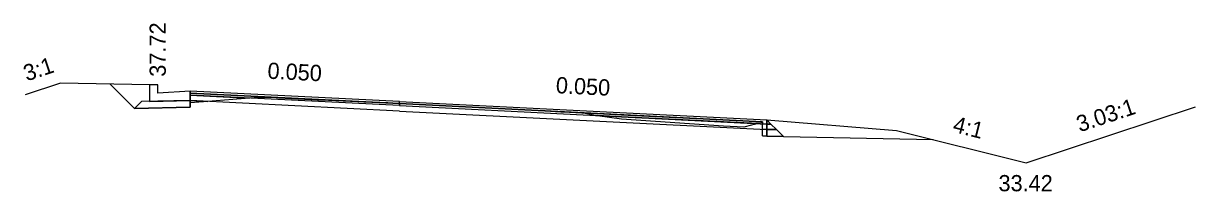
# Model space of a CAD drawing. Extents: x 2192944 to 2203363, y 83241 to 89279.
# Drawn here: x 2203233 to 2203305.3, y 86249.9 to 86260.2 of the extents above; entities that cross this region are included whole.
import ezdxf

# ---------------------------------------------------------------- set-up
doc = ezdxf.new("R2010")
doc.units = 0
for name, color, linetype in [('Prop CMT Conc Surface', 7, 'Continuous'), ('Prop CMT Concrete Structures', 7, 'Continuous'), ('Prop CMT Pvmt Course 1', 7, 'Continuous'), ('Prop CMT Pvmt Course 1 CG', 7, 'Continuous'), ('Prop CMT Pvmt Course 1 Wedge', 7, 'Continuous'), ('Prop CMT Pvmt Course 2', 7, 'Continuous'), ('Prop CMT Pvmt Course 2 Wedge', 7, 'Continuous'), ('Prop CMT Pvmt Course 3', 7, 'Continuous'), ('Prop CMT Pvmt Course 3 Wedge', 7, 'Continuous'), ('Prop CMT Pvmt Surface', 7, 'Continuous'), ('Prop CMT Pvmt Surface Shoulder', 7, 'Continuous'), ('Prop CMT Pvmt Wedge Surface 1', 7, 'Continuous'), ('Prop CMT Pvmt Wedge Surface 2', 7, 'Continuous'), ('Prop CMT Pvmt Wedge Surface 3', 7, 'Continuous'), ('Prop CMT Shld Paved Course 1', 7, 'Continuous'), ('Prop CMT Shld Paved Course 2', 7, 'Continuous'), ('Prop CMT Shld Paved Course 3', 7, 'Continuous'), ('Prop CMT Slope Grass', 7, 'Continuous'), ('Prop CMT Subgrade Earthwork', 7, 'Continuous'), ('Prop XS Ditch Standard Text', 7, 'Continuous'), ('Prop XS Hydro Elevations', 7, 'Continuous'), ('Prop XS SE Text', 7, 'Continuous'), ('Prop XS Side Slope Text', 7, 'Continuous')]:
    doc.layers.add(name, color=color, linetype=linetype)

msp = doc.modelspace()

# ---------------------------------------------------------------- linework, layer by layer
at = {"layer": 'Prop CMT Conc Surface'}
for points in [[(2203241.321, 86255.938), (2203241.32, 86256.438), (2203240.82, 86256.438)], [(2203243.321, 86256.058), (2203241.321, 86255.938)]]:
    msp.add_lwpolyline(points, dxfattribs=at)
at = {"layer": 'Prop CMT Concrete Structures'}
for points in [[(2203243.321, 86256.058), (2203241.321, 86255.938), (2203241.32, 86256.438), (2203240.82, 86256.438)], [(2203240.82, 86256.438), (2203240.821, 86255.424), (2203243.321, 86255.474)], [(2203243.321, 86255.474), (2203243.321, 86256.058)]]:
    msp.add_lwpolyline(points, dxfattribs=at)
at = {"layer": 'Prop CMT Pvmt Course 1'}
for points in [[(2203256.225, 86255.412), (2203243.321, 86256.058)], [(2203243.321, 86256.058), (2203243.321, 86255.808), (2203243.321, 86255.808), (2203243.321, 86255.933)], [(2203243.321, 86255.933), (2203256.225, 86255.287)], [(2203256.225, 86255.162), (2203256.225, 86255.412)], [(2203256.225, 86255.412), (2203278.888, 86254.279)], [(2203256.225, 86255.162), (2203256.225, 86255.412)], [(2203256.225, 86255.287), (2203256.225, 86255.162), (2203256.225, 86255.162)], [(2203278.619, 86254.168), (2203256.225, 86255.287)], [(2203256.225, 86255.287), (2203256.225, 86255.162), (2203256.225, 86255.162)], [(2203278.619, 86254.043), (2203278.619, 86254.168)], [(2203278.888, 86254.029), (2203278.619, 86254.043)], [(2203278.888, 86254.279), (2203278.888, 86254.029)]]:
    msp.add_lwpolyline(points, dxfattribs=at)
at = {"layer": 'Prop CMT Pvmt Course 1 CG'}
for points in [[(2203243.321, 86255.474), (2203240.321, 86255.414), (2203239.896, 86254.989)], [(2203243.321, 86255.058), (2203243.321, 86255.474)], [(2203239.896, 86254.989), (2203243.321, 86255.058)]]:
    msp.add_lwpolyline(points, dxfattribs=at)
at = {"layer": 'Prop CMT Pvmt Course 1 Wedge'}
for points in [[(2203243.321, 86255.933), (2203247.558, 86255.721), (2203248.177, 86255.69), (2203248.63, 86255.667), (2203248.668, 86255.665), (2203248.781, 86255.66), (2203251.17, 86255.54), (2203251.408, 86255.528), (2203253.673, 86255.415), (2203254.034, 86255.397), (2203255.521, 86255.323)], [(2203243.321, 86255.808), (2203243.321, 86255.933)], [(2203255.521, 86255.323), (2203254.034, 86255.391), (2203253.673, 86255.407), (2203251.408, 86255.494), (2203251.17, 86255.503), (2203248.781, 86255.627), (2203248.668, 86255.633), (2203248.63, 86255.634), (2203248.177, 86255.653), (2203247.558, 86255.671), (2203246.981, 86255.625), (2203243.321, 86255.808)], [(2203278.619, 86254.103), (2203278.397, 86254.054), (2203277.937, 86254.077), (2203277.477, 86254.1), (2203276.221, 86254.163), (2203269.92, 86254.478), (2203268.435, 86254.552), (2203268.322, 86254.558), (2203267.486, 86254.716), (2203266.345, 86254.771), (2203266.187, 86254.781), (2203265.207, 86254.838)], [(2203265.207, 86254.838), (2203266.187, 86254.789)], [(2203266.187, 86254.789), (2203266.345, 86254.781), (2203267.486, 86254.724), (2203268.435, 86254.677), (2203269.92, 86254.603), (2203276.221, 86254.288), (2203277.477, 86254.225), (2203277.937, 86254.202), (2203278.619, 86254.168)], [(2203278.619, 86254.168), (2203278.619, 86254.103)]]:
    msp.add_lwpolyline(points, dxfattribs=at)
at = {"layer": 'Prop CMT Pvmt Course 2'}
for points in [[(2203243.321, 86255.474), (2203243.321, 86255.474), (2203243.321, 86255.808), (2203243.321, 86255.808)], [(2203243.321, 86255.808), (2203243.321, 86255.474)], [(2203278.619, 86253.709), (2203278.619, 86254.043)], [(2203278.619, 86254.043), (2203278.888, 86254.029)], [(2203278.888, 86254.029), (2203278.888, 86253.696)], [(2203278.888, 86253.696), (2203278.619, 86253.709)]]:
    msp.add_lwpolyline(points, dxfattribs=at)
at = {"layer": 'Prop CMT Pvmt Course 2 Wedge'}
for points in [[(2203243.321, 86255.808), (2203246.981, 86255.625)], [(2203243.321, 86255.474), (2203243.321, 86255.808)], [(2203246.981, 86255.625), (2203244.41, 86255.42), (2203243.321, 86255.474)], [(2203278.397, 86254.054), (2203277.937, 86253.953), (2203277.477, 86253.829), (2203276.221, 86253.897), (2203269.92, 86254.32), (2203268.435, 86254.536), (2203268.323, 86254.558)], [(2203268.323, 86254.558), (2203268.435, 86254.552)], [(2203268.435, 86254.552), (2203269.92, 86254.478), (2203276.221, 86254.163), (2203277.477, 86254.1), (2203277.937, 86254.077), (2203278.397, 86254.054)]]:
    msp.add_lwpolyline(points, dxfattribs=at)
at = {"layer": 'Prop CMT Pvmt Course 3'}
for points in [[(2203243.321, 86255.474), (2203243.321, 86255.474), (2203243.321, 86255.058), (2203243.321, 86255.058)], [(2203243.321, 86255.058), (2203243.321, 86255.474)], [(2203278.619, 86253.709), (2203278.888, 86253.696)], [(2203278.619, 86253.293), (2203278.619, 86253.709)], [(2203278.888, 86253.279), (2203278.619, 86253.293)], [(2203278.888, 86253.696), (2203278.888, 86253.279)]]:
    msp.add_lwpolyline(points, dxfattribs=at)
at = {"layer": 'Prop CMT Pvmt Course 3 Wedge'}
for points in [[(2203243.321, 86255.474), (2203244.41, 86255.42)], [(2203243.321, 86255.333), (2203243.321, 86255.474)], [(2203244.41, 86255.42), (2203243.321, 86255.333)]]:
    msp.add_lwpolyline(points, dxfattribs=at)
at = {"layer": 'Prop CMT Pvmt Surface'}
for points in [[(2203256.225, 86255.412), (2203243.321, 86256.058)], [(2203256.225, 86255.412), (2203278.888, 86254.279)]]:
    msp.add_lwpolyline(points, dxfattribs=at)
at = {"layer": 'Prop CMT Pvmt Surface Shoulder'}
msp.add_lwpolyline([(2203278.888, 86254.279), (2203278.888, 86254.279)], dxfattribs=at)
at = {"layer": 'Prop CMT Pvmt Wedge Surface 1'}
for points in [[(2203243.321, 86255.808), (2203243.321, 86256.058)], [(2203256.225, 86255.287), (2203243.321, 86255.933)], [(2203243.321, 86255.933), (2203243.321, 86255.808), (2203243.321, 86255.808)], [(2203256.225, 86255.287), (2203278.619, 86254.168)], [(2203278.619, 86254.168), (2203278.619, 86254.043)], [(2203278.619, 86254.043), (2203278.888, 86254.029)], [(2203278.888, 86254.029), (2203278.888, 86254.279)]]:
    msp.add_lwpolyline(points, dxfattribs=at)
at = {"layer": 'Prop CMT Pvmt Wedge Surface 2'}
for points in [[(2203243.321, 86255.808), (2203243.321, 86256.058)], [(2203256.225, 86255.162), (2203243.321, 86255.808)], [(2203256.225, 86255.162), (2203278.888, 86254.029)], [(2203278.888, 86254.029), (2203278.888, 86254.279)]]:
    msp.add_lwpolyline(points, dxfattribs=at)
at = {"layer": 'Prop CMT Pvmt Wedge Surface 3'}
for points in [[(2203243.321, 86255.474), (2203243.321, 86256.058)], [(2203256.225, 86254.829), (2203243.321, 86255.474)], [(2203256.225, 86254.829), (2203278.888, 86253.696)], [(2203278.888, 86253.696), (2203278.888, 86254.279)]]:
    msp.add_lwpolyline(points, dxfattribs=at)
at = {"layer": 'Prop CMT Shld Paved Course 1'}
for points in [[(2203278.888, 86254.279), (2203278.888, 86254.279)], [(2203278.888, 86254.279), (2203279.143, 86254.024)], [(2203278.888, 86254.029), (2203278.888, 86254.279)], [(2203279.143, 86254.024), (2203278.888, 86254.029)]]:
    msp.add_lwpolyline(points, dxfattribs=at)
at = {"layer": 'Prop CMT Shld Paved Course 2'}
for points in [[(2203278.888, 86254.029), (2203279.143, 86254.024), (2203279.483, 86253.684)], [(2203278.888, 86253.696), (2203278.888, 86254.029)], [(2203279.483, 86253.684), (2203278.888, 86253.696)]]:
    msp.add_lwpolyline(points, dxfattribs=at)
at = {"layer": 'Prop CMT Shld Paved Course 3'}
for points in [[(2203278.888, 86253.696), (2203279.483, 86253.684)], [(2203278.888, 86253.279), (2203278.888, 86253.696)], [(2203279.908, 86253.259), (2203278.888, 86253.279)], [(2203279.483, 86253.684), (2203279.483, 86253.684)], [(2203279.483, 86253.684), (2203279.908, 86253.259)]]:
    msp.add_lwpolyline(points, dxfattribs=at)
at = {"layer": 'Prop CMT Slope Grass'}
for points in [[(2203240.82, 86256.438), (2203235.32, 86256.548), (2203233.143, 86255.822)], [(2203278.888, 86254.279), (2203286.888, 86253.639), (2203294.888, 86251.639), (2203305.329, 86255.085)]]:
    msp.add_lwpolyline(points, dxfattribs=at)
at = {"layer": 'Prop CMT Subgrade Earthwork'}
for points in [[(2203243.321, 86255.058), (2203239.896, 86254.989), (2203238.399, 86256.486)], [(2203243.321, 86255.058), (2203243.336, 86255.334)], [(2203243.321, 86255.058), (2203243.321, 86255.058)], [(2203278.619, 86253.293), (2203278.618, 86254.102)], [(2203278.619, 86253.293), (2203278.888, 86253.279)], [(2203278.888, 86253.279), (2203279.908, 86253.259)], [(2203279.908, 86253.259), (2203289.149, 86253.074)]]:
    msp.add_lwpolyline(points, dxfattribs=at)

# ---------------------------------------------------------------- texts
at = {"layer": 'Prop XS Ditch Standard Text'}
msp.add_text('33.42', height=1, dxfattribs=at).set_placement((2203293.177, 86249.889))
at = {"layer": 'Prop XS Hydro Elevations'}
msp.add_text('37.72', height=1, rotation=90, dxfattribs=at).set_placement((2203241.821, 86256.938))
at = {"layer": 'Prop XS SE Text'}
for p in [(2203248.075, 86256.821), (2203265.859, 86255.932)]:
    msp.add_text('0.050', height=1, rotation=357.13759, dxfattribs=at).set_placement(p)
at = {"layer": 'Prop XS Side Slope Text'}
for s, rotation, p in [('3:1', 18.43323, (2203233.242, 86256.646)), ('3.03:1', 18.26289, (2203298.182, 86253.516)), ('4:1', 345.96376, (2203290.301, 86253.559))]:
    msp.add_text(s, height=1, rotation=rotation, dxfattribs=at).set_placement(p)

doc.saveas('drawing.dxf')
